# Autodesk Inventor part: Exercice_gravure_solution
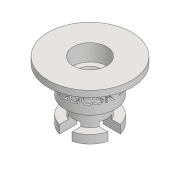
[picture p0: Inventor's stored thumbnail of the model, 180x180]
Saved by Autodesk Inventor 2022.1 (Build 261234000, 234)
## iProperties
Created: 2018-06
Part Number: Exercice_gravure_solution
Material: Générique
Document SubType Name: Modeling
Designer: Fabian Perrée
Density: 1 g/cm^3
Appearance: Par défaut
Mass: 1.1277 g
Surface Area: 16.0682 cm^2
Volume: 1.1277 cm^3
Author: Fabian Perrée
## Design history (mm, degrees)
sketch "Esquisse1"
  geometry: L1 (0, 0)-(0, 14); L2 (0, 14)-(10, 14); L3 (10, 14)-(10, 12.5); L4 (10, 12.5)-(6, 12.5); L5 (6, 12.5)-(6, 6); L6 (6, 6)-(4, 6); L7 (4, 6)-(4, 2); L8 (4, 2)-(6, 2); L9 (6, 2)-(6, 0); L10 (6, 0)-(0, 0); L11 (4, 14)-(4, 10); L12 (4, 10)-(2.25, 10); L13 (2.25, 10)-(2.25, 3); L14 (2.25, 3)-(0, 3)
  constraints: 28 end point, 12 perpendicular, 2 point on line, 2 vertical, 1 collinear
  dimensions: "d0" = 14 distance of L1.start L1.end; "d2" = 1.5 distance of L2.end L3.end; "d3" = 20 diameter of L3 L1; "d5" = 12 diameter of L5 L1; "d6" = 8 diameter of L7 L1; "d7" = 6.5 distance of L4.end L5.end; "d8" = 4 distance of L6.end L7.end; "d9" = 2 distance of L8.end L9.end (derived); "d10" = 8 diameter of L11 L1; "d11" = 4.5 diameter of L13 L1; "d12" = 4 distance of L11.start L11.end; "d13" = 3 distance between parallel lines of L10 L14
revolve "Révolution1" sketch "Esquisse1" stored, may be unused: angle "d14" = 90 deg
sketch "Esquisse2"
  geometry: L1 (6, 1.5)-(0, 1.5); L2 (0, 1.5)-(0, -1.5); L3 (0, -1.5)-(6, -1.5); L4 (6, -1.5)-(6, 1.5); L5 (0, 0)-(10, 0); C1 r 6 at (0, 0) reference; 1 further point
  constraints: 10 end point, 2 parallel, 1 horizontal, 1 horizontal alignment, 1 midpoint, 1 perpendicular, 1 tangent, 2 other
  dimensions: "d15" = 3 distance of L3.end L1.start
extrude "Extrusion1" cut sketch "Esquisse2" distance "d16" = 3; taper "d17" = 0 deg
pattern_circular "Réseau circulaire1" dims angle "d19" = 360 deg
chamfer "Chanfrein1" distance "d21" = 0.5; stored, may be unused: second distance "d22" = 2, angle "d23" = 45 deg
sketch "Esquisse3"
  geometry: C1 r 2.25 at (0, 0); A1 r 2.25 centre (0, 0) between (-1.5, -1.677) and (1.5, -1.677) reference
  constraints: 1 centre point, 1 coincident, 1 concentric
extrude "Extrusion2" cut sketch "Esquisse3" extent not by distance; stored distance "d24" = 10; taper "d25" = 0 deg
node "Plan de construction3"
sketch "Esquisse4"
  geometry: L1 (2, 17)-(2, -17); L2 (2, -17)-(-2, -17); L3 (-2, -17)-(-2, 17); L4 (-2, 17)-(2, 17); L5 (3.25, -6)-(-3.25, -6) reference; 4 further points
  constraints: 3 midpoint, 1 horizontal alignment, 1 vertical, 1 vertical alignment, 2 other
  dimensions: "d31" = 34 distance of L1.start L1.end; "d32" = 4 distance of L3.end L1.start
feature "Gravure3" sketch "Esquisse4" dims "d15" = 3, "d37" = 1, "d38" = 0
node "Solide1"
